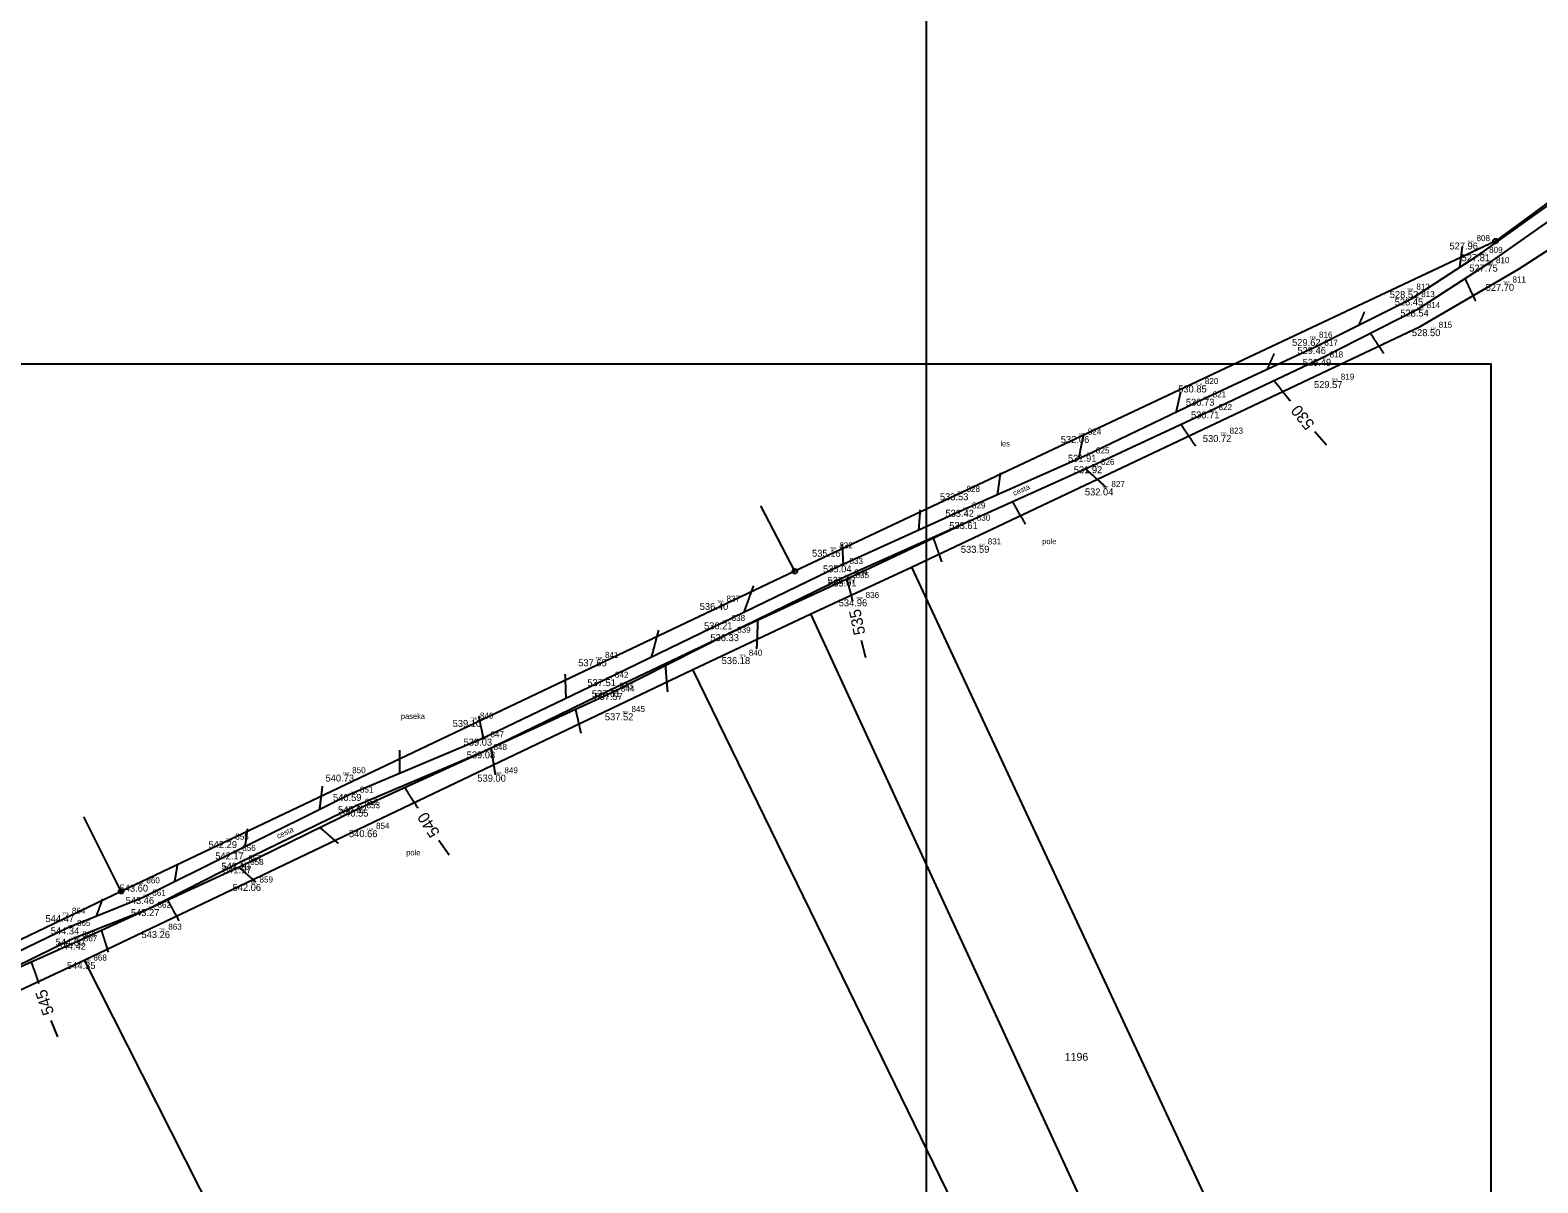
# Model space of a CAD drawing. Extents: x -604848 to -603227, y -1111879 to -1109838.
# Drawn here: x -604568.4 to -604243.7, y -1111215.2 to -1110966.8 of the extents above; entities that cross this region are included whole.
import ezdxf

# ---------------------------------------------------------------- set-up
doc = ezdxf.new("R2010")
doc.units = 0
for name, color, linetype in [('1', 7, 'Continuous'), ('10', 7, 'Continuous'), ('14', 7, 'Continuous'), ('18', 7, 'Continuous'), ('19', 7, 'Continuous'), ('20', 7, 'Continuous'), ('28', 7, 'Continuous'), ('4', 7, 'Continuous'), ('7', 7, 'Continuous'), ('9', 7, 'Continuous'), ('Default', 7, 'Continuous')]:
    doc.layers.add(name, color=color, linetype=linetype)

# ---------------------------------------------------------------- blocks, each defined once
blk = doc.blocks.new('Z105')
at = {"layer": '28'}
for radius in [0.5, 0.01]:
    blk.add_circle((0, 0), radius, dxfattribs=at)
blk = doc.blocks.new('POINT_DISPLAY')
at = {"layer": 'Default'}
blk.add_line((0, 0), (0, 0), dxfattribs=at)

msp = doc.modelspace()

# ---------------------------------------------------------------- linework, layer by layer
at = {"layer": '1'}
for p, q in [((-604232.79, -1110997.55), (-604252.82, -1111012.29)), ((-604247.83, -1111018.35), (-604223.34, -1111002.38)), ((-604252.82, -1111012.29), (-604403.71, -1111083.44)), ((-604269, -1111030.73), (-604247.83, -1111018.35)), ((-604378.63, -1111082.57), (-604269, -1111030.73)), ((-604403.71, -1111083.44), (-604548.87, -1111152.42)), ((-604400.31, -1111092.6), (-604378.63, -1111082.57)), ((-604378.63, -1111082.57), (-604301.84, -1111247.23)), ((-604425.71, -1111104.6), (-604400.31, -1111092.6)), ((-604324.43, -1111256.97), (-604400.31, -1111092.6)), ((-604556.81, -1111167.23), (-604425.71, -1111104.6)), ((-604346.25, -1111267.64), (-604425.71, -1111104.6)), ((-604548.87, -1111152.42), (-604671.12, -1111211.37)), ((-604684.78, -1111226.85), (-604556.81, -1111167.23)), ((-604556.81, -1111167.23), (-604474.96, -1111329.05))]:
    msp.add_line(p, q, dxfattribs=at)
for points in [[(-603781.41, -1111422.77), (-603781.41, -1110582.77), (-604375.41, -1110582.77), (-604375.41, -1111422.77), (-603781.41, -1111422.77)], [(-604253.71, -1111878.79), (-604253.71, -1111038.79), (-604847.71, -1111038.79), (-604847.71, -1111878.79), (-604253.71, -1111878.79)]]:
    msp.add_lwpolyline(points, dxfattribs=at)
at = {"layer": '10'}
for p, q in [((-604403.71, -1111083.44), (-604411.03, -1111069.33)), ((-604366.52, -1111072.85), (-604392.64, -1111085.22)), ((-604392.64, -1111085.22), (-604418.15, -1111097)), ((-604418.15, -1111097), (-604443.18, -1111109.67)), ((-604443.18, -1111109.67), (-604470.63, -1111122.27)), ((-604470.63, -1111122.27), (-604497.99, -1111134.81)), ((-604497.99, -1111134.81), (-604523.06, -1111147.05)), ((-604548.87, -1111152.42), (-604556.88, -1111136.34)), ((-604523.06, -1111147.05), (-604543.02, -1111156.25)), ((-604543.02, -1111156.25), (-604558.89, -1111163.5)), ((-604558.89, -1111163.5), (-604583.48, -1111174.51))]:
    msp.add_line(p, q, dxfattribs=at)
at = {"layer": '4'}
for p, q in [((-604256.17, -1111015.13), (-604239.83, -1111003.42)), ((-604238.22, -1111005.74), (-604254.7, -1111017.36)), ((-604270.79, -1111024.66), (-604256.17, -1111015.13)), ((-604254.7, -1111017.36), (-604269.63, -1111027.04)), ((-604291.66, -1111035.11), (-604270.79, -1111024.66)), ((-604269.63, -1111027.04), (-604290.52, -1111037.67)), ((-604315.72, -1111046.27), (-604291.66, -1111035.11)), ((-604290.52, -1111037.67), (-604314.45, -1111049.01)), ((-604340.86, -1111058.35), (-604315.72, -1111046.27)), ((-604314.45, -1111049.01), (-604339.78, -1111060.82)), ((-604367.57, -1111070.2), (-604340.86, -1111058.35)), ((-604339.78, -1111060.82), (-604366.52, -1111072.85)), ((-604393.95, -1111082.19), (-604367.57, -1111070.2)), ((-604366.52, -1111072.85), (-604392.92, -1111084.65)), ((-604419.34, -1111094.46), (-604393.95, -1111082.19)), ((-604392.92, -1111084.65), (-604418.15, -1111097)), ((-604444.48, -1111106.7), (-604419.34, -1111094.46)), ((-604418.15, -1111097), (-604443.5, -1111109.07)), ((-604471.29, -1111119.52), (-604444.48, -1111106.7)), ((-604443.5, -1111109.07), (-604470.63, -1111122.27)), ((-604499.41, -1111131.44), (-604471.29, -1111119.52)), ((-604470.63, -1111122.27), (-604498.35, -1111134.07)), ((-604524.76, -1111144.03), (-604499.41, -1111131.44)), ((-604498.35, -1111134.07), (-604523.43, -1111146.27)), ((-604544.13, -1111153.64), (-604524.76, -1111144.03)), ((-604523.43, -1111146.27), (-604543.02, -1111156.25)), ((-604560.36, -1111160.19), (-604544.13, -1111153.64)), ((-604543.02, -1111156.25), (-604559.22, -1111162.63)), ((-604584.67, -1111171.99), (-604560.36, -1111160.19)), ((-604559.22, -1111162.63), (-604583.48, -1111174.51))]:
    msp.add_line(p, q, dxfattribs=at)
at = {"layer": '7'}
for p, q in [((-604289.22, -1111056.27), (-604291.75, -1111053.38)), ((-604388.44, -1111102.09), (-604389.38, -1111098.37)), ((-604478.18, -1111144.64), (-604480.38, -1111141.49)), ((-604562.5, -1111183.8), (-604563.9, -1111180.22))]:
    msp.add_line(p, q, dxfattribs=at)
for points in [[(-604260.48, -1111017.94), (-604260.29, -1111016.43), (-604260.09, -1111014.93), (-604259.9, -1111013.42)], [(-604259.38, -1111020.4), (-604258.63, -1111021.99), (-604257.88, -1111023.59), (-604257.12, -1111025.19)], [(-604282.19, -1111030.37), (-604281.79, -1111029.43), (-604281.39, -1111028.49), (-604280.99, -1111027.56)], [(-604279.77, -1111032.2), (-604278.81, -1111033.64), (-604277.86, -1111035.07), (-604276.9, -1111036.5)], [(-604301.93, -1111039.87), (-604301.42, -1111038.74), (-604300.91, -1111037.61), (-604300.4, -1111036.48)], [(-604300.51, -1111042.4), (-604299.34, -1111043.86), (-604298.18, -1111045.32), (-604297.01, -1111046.77)], [(-604321.54, -1111049.06), (-604321.22, -1111047.63), (-604320.9, -1111046.2), (-604320.57, -1111044.77)], [(-604342.54, -1111059.09), (-604342.18, -1111057.32), (-604341.82, -1111055.56), (-604341.46, -1111053.79)], [(-604320.55, -1111051.85), (-604319.51, -1111053.4), (-604318.46, -1111054.95), (-604317.42, -1111056.5)], [(-604360.04, -1111066.86), (-604359.82, -1111065.31), (-604359.61, -1111063.76), (-604359.39, -1111062.21)], [(-604341.08, -1111061.4), (-604339.64, -1111062.69), (-604338.21, -1111063.97), (-604336.77, -1111065.25)], [(-604377, -1111074.49), (-604376.9, -1111073.05), (-604376.79, -1111071.61), (-604376.69, -1111070.17)], [(-604356.87, -1111068.51), (-604355.94, -1111070.1), (-604355.01, -1111071.69), (-604354.08, -1111073.27)], [(-604373.9, -1111076.34), (-604373.3, -1111078.04), (-604372.7, -1111079.74), (-604372.1, -1111081.44)], [(-604393.25, -1111081.87), (-604393.33, -1111080.46), (-604393.4, -1111079.05), (-604393.47, -1111077.63)], [(-604414.63, -1111092.18), (-604413.95, -1111090.32), (-604413.28, -1111088.46), (-604412.61, -1111086.6)], [(-604392.52, -1111085.16), (-604392.11, -1111086.74), (-604391.7, -1111088.33), (-604391.29, -1111089.91)], [(-604434.55, -1111101.86), (-604434.04, -1111099.95), (-604433.54, -1111098.04), (-604433.03, -1111096.12)], [(-604411.73, -1111094.04), (-604411.81, -1111096.07), (-604411.89, -1111098.1), (-604411.97, -1111100.13)], [(-604452.99, -1111110.77), (-604453.05, -1111109.05), (-604453.11, -1111107.32), (-604453.17, -1111105.6)], [(-604431.63, -1111103.82), (-604431.48, -1111105.68), (-604431.33, -1111107.54), (-604431.17, -1111109.4)], [(-604470.81, -1111119.29), (-604471.13, -1111117.74), (-604471.46, -1111116.19), (-604471.78, -1111114.64)], [(-604450.98, -1111113.24), (-604450.59, -1111114.95), (-604450.21, -1111116.66), (-604449.82, -1111118.36)], [(-604488.82, -1111126.95), (-604488.81, -1111125.3), (-604488.8, -1111123.66), (-604488.79, -1111122.01)], [(-604469.16, -1111121.59), (-604468.87, -1111123.48), (-604468.58, -1111125.38), (-604468.29, -1111127.28)], [(-604506.06, -1111134.74), (-604505.86, -1111133.07), (-604505.66, -1111131.41), (-604505.45, -1111129.75)], [(-604487.77, -1111130.12), (-604486.83, -1111131.58), (-604485.9, -1111133.03), (-604484.96, -1111134.49)], [(-604505.96, -1111138.7), (-604504.67, -1111139.82), (-604503.38, -1111140.95), (-604502.08, -1111142.07)], [(-604522.1, -1111142.71), (-604521.94, -1111141.45), (-604521.78, -1111140.2), (-604521.62, -1111138.95)], [(-604537.28, -1111150.24), (-604537.07, -1111149.06), (-604536.87, -1111147.87), (-604536.66, -1111146.69)], [(-604523.47, -1111147.24), (-604522.29, -1111148.26), (-604521.12, -1111149.28), (-604519.94, -1111150.31)], [(-604554.13, -1111157.68), (-604553.68, -1111156.45), (-604553.24, -1111155.23), (-604552.79, -1111154.01)], [(-604538.85, -1111154.33), (-604538.03, -1111155.81), (-604537.22, -1111157.29), (-604536.4, -1111158.77)], [(-604553.11, -1111160.86), (-604552.62, -1111162.41), (-604552.13, -1111163.95), (-604551.65, -1111165.5)], [(-604568.21, -1111167.67), (-604567.66, -1111169.22), (-604567.12, -1111170.76), (-604566.57, -1111172.31)]]:
    msp.add_open_spline(points, degree=2, dxfattribs=at)

# ---------------------------------------------------------------- block references
at = {"layer": '18'}
for p in [(-604258.88, -1111012.6), (-604256.17, -1111015.13), (-604254.7, -1111017.36), (-604251.14, -1111021.52), (-604271.85, -1111023.05), (-604270.79, -1111024.66), (-604269.63, -1111027.04), (-604267.05, -1111031.27), (-604292.82, -1111033.39), (-604291.66, -1111035.11), (-604290.52, -1111037.67), (-604317.4, -1111043.41), (-604288.12, -1111042.46), (-604315.72, -1111046.27), (-604314.45, -1111049.01), (-604342.63, -1111054.29), (-604312.08, -1111054.09), (-604340.86, -1111058.35), (-604339.78, -1111060.82), (-604368.75, -1111066.63), (-604337.54, -1111065.59), (-604367.57, -1111070.2), (-604366.52, -1111072.85), (-604396.14, -1111078.82), (-604364.18, -1111077.96), (-604393.95, -1111082.19), (-604392.92, -1111084.65), (-604392.64, -1111085.22), (-604390.47, -1111089.5), (-604420.44, -1111090.29), (-604419.34, -1111094.46), (-604418.15, -1111097), (-604446.62, -1111102.41), (-604415.64, -1111101.95), (-604444.48, -1111106.7), (-604443.5, -1111109.07), (-604443.18, -1111109.67), (-604473.55, -1111115.5), (-604440.91, -1111114.06), (-604471.29, -1111119.52), (-604470.63, -1111122.27), (-604501.08, -1111127.26), (-604468.29, -1111127.28), (-604499.41, -1111131.44), (-604498.35, -1111134.07), (-604497.99, -1111134.81), (-604526.26, -1111141.58), (-604495.94, -1111139.24), (-604524.76, -1111144.03), (-604523.43, -1111146.27), (-604523.06, -1111147.05), (-604545.41, -1111150.99), (-604521.04, -1111150.82), (-604544.13, -1111153.64), (-604561.45, -1111157.55), (-604543.02, -1111156.25), (-604560.36, -1111160.19), (-604540.69, -1111160.99), (-604559.22, -1111162.63), (-604558.89, -1111163.5), (-604556.82, -1111167.64)]:
    msp.add_blockref('POINT_DISPLAY', p, dxfattribs=at)
at = {"layer": '28'}
for p in [(-604252.82, -1111012.29), (-604403.71, -1111083.44), (-604548.87, -1111152.42)]:
    msp.add_blockref('Z105', p, dxfattribs=at)

# ---------------------------------------------------------------- texts
at = {"layer": '14'}
msp.add_text('1196', height=1.7, dxfattribs=at).set_placement((-604345.58, -1111188.93))
at = {"layer": '18'}
for s, p in [('TER', (-604258.88, -1111012.6)), ('CES', (-604256.17, -1111015.13)), ('CES', (-604254.7, -1111017.36)), ('TER', (-604251.14, -1111021.52)), ('TER', (-604271.85, -1111023.05)), ('CES', (-604270.79, -1111024.66)), ('CES', (-604269.63, -1111027.04)), ('TER', (-604267.05, -1111031.27)), ('TER', (-604292.82, -1111033.39)), ('CES', (-604291.66, -1111035.11)), ('CES', (-604290.52, -1111037.67)), ('TER', (-604317.4, -1111043.41)), ('TER', (-604288.12, -1111042.46)), ('CES', (-604315.72, -1111046.27)), ('CES', (-604314.45, -1111049.01)), ('TER', (-604342.63, -1111054.29)), ('TER', (-604312.08, -1111054.09)), ('CES', (-604340.86, -1111058.35)), ('CES', (-604339.78, -1111060.82)), ('TER', (-604368.75, -1111066.63)), ('TER', (-604337.54, -1111065.59)), ('CES', (-604367.57, -1111070.2)), ('CES', (-604366.52, -1111072.85)), ('TER', (-604396.14, -1111078.82)), ('TER', (-604364.18, -1111077.96)), ('CES', (-604393.95, -1111082.19)), ('CES', (-604392.92, -1111084.65)), ('POL', (-604392.64, -1111085.22)), ('TER', (-604420.44, -1111090.29)), ('TER', (-604390.47, -1111089.5)), ('CES', (-604419.34, -1111094.46)), ('CES', (-604418.15, -1111097)), ('TER', (-604446.62, -1111102.41)), ('TER', (-604415.64, -1111101.95)), ('CES', (-604444.48, -1111106.7)), ('CES', (-604443.5, -1111109.07)), ('POL', (-604443.18, -1111109.67)), ('TER', (-604473.55, -1111115.5)), ('TER', (-604440.91, -1111114.06)), ('CES', (-604471.29, -1111119.52)), ('CES', (-604470.63, -1111122.27)), ('TER', (-604501.08, -1111127.26)), ('TER', (-604468.29, -1111127.28)), ('CES', (-604499.41, -1111131.44)), ('CES', (-604498.35, -1111134.07)), ('POL', (-604497.99, -1111134.81)), ('TER', (-604495.94, -1111139.24)), ('TER', (-604526.26, -1111141.58)), ('CES', (-604524.76, -1111144.03)), ('CES', (-604523.43, -1111146.27)), ('POL', (-604523.06, -1111147.05)), ('TER', (-604545.41, -1111150.99)), ('TER', (-604521.04, -1111150.82)), ('CES', (-604544.13, -1111153.64)), ('TER', (-604561.45, -1111157.55)), ('CES', (-604543.02, -1111156.25)), ('CES', (-604560.36, -1111160.19)), ('TER', (-604540.69, -1111160.99)), ('CES', (-604559.22, -1111162.63)), ('POL', (-604558.89, -1111163.5)), ('TER', (-604556.82, -1111167.64))]:
    msp.add_text(s, height=0.5, dxfattribs=at).set_placement(p)
at = {"layer": '19'}
for s, p in [('808', (-604256.88, -1111012.3)), ('809', (-604254.17, -1111014.83)), ('810', (-604252.7, -1111017.06)), ('812', (-604269.85, -1111022.75)), ('811', (-604249.14, -1111021.22)), ('813', (-604268.79, -1111024.36)), ('814', (-604267.63, -1111026.74)), ('815', (-604265.05, -1111030.97)), ('816', (-604290.82, -1111033.09)), ('817', (-604289.66, -1111034.81)), ('818', (-604288.52, -1111037.37)), ('819', (-604286.12, -1111042.16)), ('820', (-604315.4, -1111043.1)), ('821', (-604313.72, -1111045.97)), ('822', (-604312.45, -1111048.71)), ('824', (-604340.63, -1111053.99)), ('823', (-604310.08, -1111053.79)), ('825', (-604338.86, -1111058.05)), ('826', (-604337.78, -1111060.52)), ('827', (-604335.54, -1111065.29)), ('828', (-604366.75, -1111066.33)), ('829', (-604365.57, -1111069.9)), ('830', (-604364.52, -1111072.55)), ('831', (-604362.18, -1111077.66)), ('832', (-604394.14, -1111078.52)), ('833', (-604391.95, -1111081.89)), ('834', (-604390.92, -1111084.35)), ('835', (-604390.64, -1111084.92)), ('837', (-604418.44, -1111089.99)), ('836', (-604388.47, -1111089.2)), ('838', (-604417.34, -1111094.16)), ('839', (-604416.15, -1111096.7)), ('841', (-604444.62, -1111102.11)), ('840', (-604413.64, -1111101.65)), ('842', (-604442.48, -1111106.4)), ('843', (-604441.5, -1111108.77)), ('844', (-604441.18, -1111109.37)), ('845', (-604438.91, -1111113.76)), ('846', (-604471.55, -1111115.2)), ('847', (-604469.29, -1111119.22)), ('848', (-604468.63, -1111121.96)), ('850', (-604499.08, -1111126.96)), ('849', (-604466.29, -1111126.98)), ('851', (-604497.41, -1111131.14)), ('852', (-604496.35, -1111133.77)), ('853', (-604495.99, -1111134.51)), ('854', (-604493.94, -1111138.94)), ('855', (-604524.26, -1111141.28)), ('856', (-604522.76, -1111143.73)), ('857', (-604521.43, -1111145.97)), ('858', (-604521.06, -1111146.75)), ('860', (-604543.41, -1111150.69)), ('859', (-604519.04, -1111150.52)), ('861', (-604542.13, -1111153.34)), ('862', (-604541.02, -1111155.95)), ('864', (-604559.45, -1111157.25)), ('865', (-604558.36, -1111159.89)), ('866', (-604557.22, -1111162.33)), ('863', (-604538.69, -1111160.69)), ('867', (-604556.89, -1111163.2)), ('868', (-604554.82, -1111167.34))]:
    msp.add_text(s, height=1.3, dxfattribs=at).set_placement(p)
at = {"layer": '20'}
for s, p in [('527.96 ', (-604262.72, -1111014.1)), ('527.81 ', (-604260.1, -1111016.63)), ('527.75 ', (-604258.46, -1111018.86)), ('527.70 ', (-604254.92, -1111023.02)), ('528.52 ', (-604275.58, -1111024.55)), ('528.45 ', (-604274.51, -1111026.16)), ('528.54 ', (-604273.31, -1111028.54)), ('528.50 ', (-604270.81, -1111032.77)), ('529.62 ', (-604296.62, -1111034.89)), ('529.46 ', (-604295.47, -1111036.61)), ('529.49 ', (-604294.33, -1111039.17)), ('530.85 ', (-604321.15, -1111044.91)), ('529.57 ', (-604291.9, -1111043.96)), ('530.73 ', (-604319.49, -1111047.77)), ('530.71 ', (-604318.4, -1111050.51)), ('532.06 ', (-604346.44, -1111055.79)), ('530.72 ', (-604315.84, -1111055.59)), ('531.91 ', (-604344.9, -1111059.85)), ('531.92 ', (-604343.64, -1111062.32)), ('533.53 ', (-604372.48, -1111068.13)), ('532.04 ', (-604341.25, -1111067.09)), ('533.42 ', (-604371.29, -1111071.7)), ('533.61 ', (-604370.47, -1111074.35)), ('535.16 ', (-604400.02, -1111080.32)), ('533.59 ', (-604367.96, -1111079.46)), ('535.04 ', (-604397.66, -1111083.69)), ('535.07 ', (-604396.68, -1111086.15)), ('535.01 ', (-604396.58, -1111086.72)), ('534.96 ', (-604394.28, -1111091)), ('536.40 ', (-604424.21, -1111091.79)), ('536.21 ', (-604423.29, -1111095.96)), ('536.33 ', (-604421.91, -1111098.5)), ('537.65 ', (-604450.39, -1111103.91)), ('536.18 ', (-604419.49, -1111103.45)), ('537.51 ', (-604448.41, -1111108.2)), ('537.61 ', (-604447.46, -1111110.57)), ('537.57 ', (-604446.93, -1111111.17)), ('539.10 ', (-604477.44, -1111117)), ('537.52 ', (-604444.65, -1111115.56)), ('539.03 ', (-604475.08, -1111121.02)), ('539.08 ', (-604474.42, -1111123.77)), ('540.73 ', (-604504.82, -1111128.76)), ('539.00 ', (-604472.11, -1111128.78)), ('540.59 ', (-604503.21, -1111132.94)), ('540.62 ', (-604502.12, -1111135.57)), ('540.55 ', (-604501.72, -1111136.31)), ('542.29 ', (-604530.03, -1111143.08)), ('540.66 ', (-604499.77, -1111140.74)), ('542.17 ', (-604528.57, -1111145.53)), ('542.10 ', (-604527.26, -1111147.77)), ('541.97 ', (-604526.91, -1111148.55)), ('543.60 ', (-604549.18, -1111152.49)), ('542.06 ', (-604524.84, -1111152.32)), ('543.46 ', (-604547.88, -1111155.14)), ('544.47 ', (-604565.14, -1111159.05)), ('543.27 ', (-604546.74, -1111157.75)), ('544.34 ', (-604564.01, -1111161.69)), ('543.26 ', (-604544.46, -1111162.49)), ('544.30 ', (-604562.94, -1111164.13)), ('544.42 ', (-604562.57, -1111165)), ('544.35 ', (-604560.52, -1111169.14))]:
    msp.add_text(s, height=1.5, dxfattribs=at).set_placement(p)
at = {"layer": '7'}
for s, rotation, p in [('530', 128.7, (-604291.63, -1111051.7)), ('535', 101.7, (-604388.52, -1111096.89)), ('540', 122.4, (-604480.09, -1111139.8)), ('545', 108.9, (-604563.24, -1111178.61))]:
    msp.add_text(s, height=2.5, rotation=rotation, dxfattribs=at).set_placement(p)
at = {"layer": '9'}
for s, p in [('les', (-604359.45, -1111056.54)), ('pole', (-604350.43, -1111077.6)), ('paseka', (-604488.58, -1111115.27)), ('pole', (-604487.42, -1111144.67))]:
    msp.add_text(s, height=1.2, dxfattribs=at).set_placement(p)
for rotation, p in [(23.4, (-604356.46, -1111067.21)), (26.1, (-604515.01, -1111141.15))]:
    msp.add_text('cesta', height=1.2, rotation=rotation, dxfattribs=at).set_placement(p)

doc.saveas('drawing.dxf')
